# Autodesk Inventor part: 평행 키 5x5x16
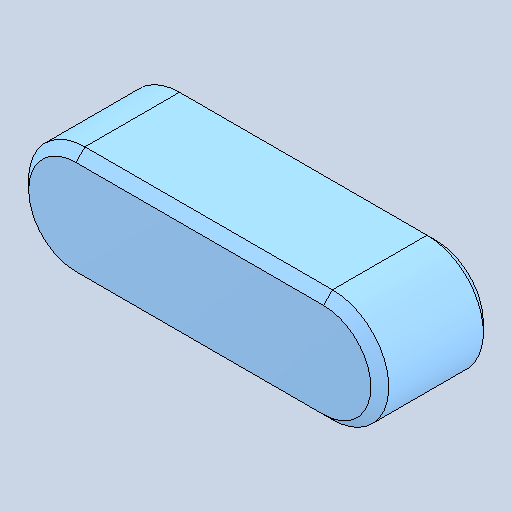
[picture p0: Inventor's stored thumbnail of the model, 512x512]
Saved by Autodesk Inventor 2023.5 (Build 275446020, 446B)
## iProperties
Created: 2026-07
Part Number: 평행 키 5x5x16
Material: 강철, 연강
Description: 키 및 해당 키홈
Document SubType Name: Modeling
Designer: 1강의실14
Density: 7.85 g/cm^3
Appearance: 기본값
Author: jhkim
Sending System: Autodesk Inventor 2027
Preprocessor: ST-DEVELOPER v20.1
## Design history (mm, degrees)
node "평행 키 5x5x161"
node "솔리드1"
body "Solid1"
